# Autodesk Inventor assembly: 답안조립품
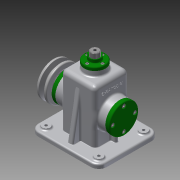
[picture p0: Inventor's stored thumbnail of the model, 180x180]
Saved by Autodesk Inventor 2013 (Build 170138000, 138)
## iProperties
Created: 2016-01
Part Number: 답안조립품
Document SubType Name: Assembly
Designer: Administrator
Author: Administrator
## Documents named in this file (19)
- C:\Users\Administrator\Desktop\460127V1014\답안조립품.iam
- C:\Users\Administrator\Desktop\460127V1014\본체.ipt
- C:\Users\Administrator\Desktop\460127V1014\V-벨트풀리.ipt
- C:\Users\Administrator\Desktop\460127V1014\고정핀.ipt
- C:\Users\Administrator\Desktop\460127V1014\뒤커버.ipt
- C:\Users\Administrator\Desktop\460127V1014\링크.ipt
- C:\Users\Administrator\Desktop\460127V1014\멈춤링 6 x 5.ipt
- C:\Users\Administrator\Desktop\460127V1014\멈춤링 15 x 1.ipt
- C:\Users\Administrator\Desktop\460127V1014\베어링 15 x 35 x 11.ipt
- C:\Users\Administrator\Desktop\460127V1014\볼트 M3 x 8.ipt
- C:\Users\Administrator\Desktop\460127V1014\볼트 M4 x 10.ipt
- C:\Users\Administrator\Desktop\460127V1014\볼트 M6 x 12.ipt
- C:\Users\Administrator\Desktop\460127V1014\상부부시.ipt
- C:\Users\Administrator\Desktop\460127V1014\슬라이드바.ipt
- C:\Users\Administrator\Desktop\460127V1014\앞커버.ipt
- C:\Users\Administrator\Desktop\460127V1014\오일실 15 25 7.ipt
- C:\Users\Administrator\Desktop\460127V1014\와셔.ipt
- C:\Users\Administrator\Desktop\460127V1014\키 5 x 5 x 14.ipt
- C:\Users\Administrator\Desktop\460127V1014\편심축.ipt
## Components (15 placed, 5 different names)
1. V-벨트풀리:1 — 각도:2
2. 고정핀:1
3. ISO 4018 M6 x 12:1
4. ISO 4762 M4 x 10:1
5. ISO 4762 M4 x 10:3
6. ISO 4762 M4 x 10:4
7. ISO 4762 M4 x 10:5
8. ISO 4762 M4 x 10:2
9. ISO 4762 M4 x 10:6
10. ISO 4762 M4 x 10:7
11. ISO 4762 M4 x 10:8
12. ISO 4762 M3 x 8:1
13. ISO 4762 M3 x 8:2
14. ISO 4762 M3 x 8:3
15. ISO 4762 M3 x 8:4
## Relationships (1: Angle 1)
- 각도:2 [Angle]: V-벨트풀리:1
